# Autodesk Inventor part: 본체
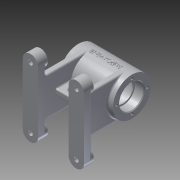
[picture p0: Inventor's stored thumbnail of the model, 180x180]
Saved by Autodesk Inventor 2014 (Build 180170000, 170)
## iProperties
Created: 2015-11
Part Number: 본체
Material: 알루미늄 6061
Document SubType Name: Modeling
Designer: Owner
Density: 2.71 g/cm^3
Appearance: 알루미늄 - 평지
Mass: 358.863 g
Surface Area: 459.993 cm^2
Volume: 132.422 cm^3
Author: Owner
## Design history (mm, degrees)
sketch "스케치1"
  geometry: L1 (-40, 50)-(-20, 50); L2 (-20, 50)-(-20, -50); L3 (-20, -50)-(-40, -50); L4 (-40, -50)-(-40, 50); L5 (40, 50)-(20, 50); L6 (20, 50)-(20, -50); L7 (20, -50)-(40, -50); L8 (40, -50)-(40, 50); 3 further points
  constraints: 16 end point, 2 parallel, 1 horizontal, 1 horizontal alignment, 1 midpoint, 1 perpendicular
  dimensions: "d0" = 100 distance of L1.end L2.end; "d1" = 20 distance of L1.start L1.end
extrude "돌출1" new body sketch "스케치1" distance "d3" = 10; taper "d4" = 0 deg
sketch "스케치2"
  geometry: L1 (68, 39.159)-(68, -46.601); L2 (0, -50)-(0, 50) reference; L3 (0, 0)-(77.376, 0); C1 r 25 at (68, 0)
  constraints: 4 end point, 2 point on line, 1 centre point, 1 perpendicular, 1 vertical
  dimensions: "d5" = 68 distance between parallel lines of L2 L1; "d6" = 50 diameter of C1
extrude "돌출2" join sketch "스케치2" stored distance "d7" = 70; taper "d8" = 0 deg
sketch "스케치3"
  geometry: C1 r 25 at (0, 0) reference; C2 r 16 at (0, 0); 1 further point
  constraints: 1 centre point, 1 coincident
  dimensions: "d9" = 32 diameter of C2
extrude "돌출3" cut sketch "스케치3" distance "d10" = 12; taper "d11" = 0 deg
sketch "스케치4"
  geometry: C1 r 16 at (0, 0) reference; 1 further point
sketch "스케치5"
  geometry: C1 r 25 at (0, 0) reference; C2 r 16 at (0, 0); 1 further point
  constraints: 1 centre point, 1 coincident
  dimensions: "d12" = 32 diameter of C2
extrude "돌출4" cut sketch "스케치5" distance "d13" = 12; taper "d14" = 0 deg
sketch "스케치6"
  geometry: C1 r 25 at (68, 0) reference; C2 r 21 at (68, 0); 1 further point
  constraints: 1 centre point, 1 coincident
  dimensions: "d15" = 42 diameter of C2
extrude "돌출5" cut sketch "스케치6" stored distance "d16" = 42; taper "d17" = 0 deg
sketch "스케치7"
  geometry: C1 r 16 at (0, 0) reference; C2 r 14 at (0, 0); 1 further point
  constraints: 1 centre point, 1 coincident
  dimensions: "d18" = 28 diameter of C2
extrude "돌출6" cut sketch "스케치7" distance "d19" = 100; taper "d20" = 0 deg
sketch "스케치9"
  geometry: L1 (-40, -50)-(-20, -50) reference; L2 (-20, -50)-(-20, 50) reference; L3 (-20, 50)-(-40, 50) reference; L4 (-40, 50)-(-40, -50) reference; 1 further point
sketch "스케치10"
  geometry: L1 (-20, -50)-(-20, 50) reference; L2 (-28, 25)-(-20, 25); L3 (-20, 25)-(-20, -25); L4 (-20, -25)-(-28, -25); L5 (-28, -25)-(-28, 25); L6 (0, 1.334)-(0, 18.077); L7 (28, 25)-(20, 25); L8 (20, 25)-(20, -25); L9 (20, -25)-(28, -25); L10 (28, -25)-(28, 25); 3 further points
  constraints: 18 end point, 5 symmetric about line, 3 parallel, 1 horizontal, 1 horizontal alignment, 1 midpoint, 1 perpendicular, 1 point on line
  dimensions: "d23" = 50 distance of L4.end L2.start; "d24" = 8 distance of L2.start L2.end
extrude "돌출7" join sketch "스케치10" stored distance "d25" = 10; taper "d26" = 0 deg
node "작업 평면2"
  node "작업 평면1"
sketch "스케치11"
  geometry: L1 (-22.5, 4)-(22.5, 4); L2 (22.5, 4)-(22.5, -4); L3 (22.5, -4)-(-22.5, -4); L4 (-22.5, -4)-(-22.5, 4); 3 further points
  constraints: 8 end point, 2 midpoint, 2 parallel, 1 horizontal, 1 horizontal alignment, 1 perpendicular, 1 vertical alignment
  dimensions: "d28" = 8 distance of L1.end L2.end; "d29" = 45 distance of L1.start L1.end
extrude "돌출8" join sketch "스케치11" stored distance "d30" = 10; taper "d31" = 0 deg
sketch "스케치12"
  geometry: L1 (40, -23)-(60, -23) reference; L2 (20, -13)-(20, -6.454); L3 (28, 6.5)-(12, 6.5); L4 (28, 13.5)-(12, 13.5); A1 r 3.5 centre (28, 10) between (28, 6.5) and (28, 13.5); A2 r 3.5 centre (12, 10) between (12, 13.5) and (12, 6.5); 1 further point
  constraints: 6 end point, 4 point on circle, 2 centre point, 2 tangent, 1 symmetric about line, 1 other
  dimensions: "d34" = 7 diameter of A1
extrude "돌출9" cut sketch "스케치12" distance "d35" = 50; taper "d36" = 0 deg
node "작업 평면4"
  node "작업 평면3"
sketch "스케치13"
  geometry: C1 r 5 at (0, 0); 1 further point
  constraints: 1 centre point, 1 coincident
  dimensions: "d38" = 10 diameter of C1
extrude "돌출10" join sketch "스케치13" stored distance "d39" = 50; taper "d40" = 0 deg
sketch "스케치14"
  geometry: L1 (68, 0)-(43.751, -14); L2 (68, 0)-(96, 0); C1 r 25 at (68, 0) reference; 1 further point
  constraints: 4 end point, 1 equal length, 1 horizontal
  dimensions: "d41" = 28 distance of L1.start L1.end; "d42" = 150 deg angle of L1 L2
node "작업 평면5"
sketch "스케치15"
  geometry: C1 r 6 at (0, 0); 1 further point
  constraints: 1 centre point
  dimensions: "d43" = 12 diameter of C1
extrude "돌출11" join sketch "스케치15" stored distance "d44" = 50; taper "d45" = 0 deg
sketch "스케치16"
  geometry: L1 (-20, 50)-(-40, 50) reference; L2 (-40, -50)-(-20, -50) reference; L3 (40, 50)-(20, 50) reference; L4 (20, -50)-(40, -50) reference; C1 r 10 at (-30, -40); C2 r 10 at (-30, 40); C3 r 10 at (30, 40); C4 r 10 at (30, -40); 5 further points
  constraints: 4 centre point, 4 midpoint, 4 vertical alignment
  dimensions: "d46" = 20 diameter of C1; "d47" = 10 distance of C1.centre point (-30, -50); "d48" = 20 diameter of C2; "d49" = 10 distance from line of L1 C2.centre; "d50" = 20 diameter of C3; "d51" = 10 distance from line of L3 C3.centre; "d52" = 20 diameter of C4; "d53" = 10 distance from line of L4 C4.centre
extrude "돌출12" join sketch "스케치16" distance "d54" = 3; taper "d55" = 0 deg
sketch "스케치17"
  geometry: C1 r 5 at (0, 0) reference; 1 further point
  constraints: 1 coincident
hole "구멍1" sketch "스케치17" at (0, 0) diameter "d56" = 5.188; stored, may be unused: countersink angle "d60" = 90 deg, drill point angle "d62" = 118 deg; dims "d57" = 20, "d58" = 4, "d59" = 2, "d61" = 20
sketch "스케치18"
  geometry: C1 r 6 at (0, 0) reference; 2 further points
  constraints: 1 coincident
hole "구멍2" sketch "스케치18" at (0, 0) diameter "d63" = 5.188; stored, may be unused: countersink angle "d67" = 90 deg, drill point angle "d69" = 118 deg; dims "d64" = 20, "d65" = 4, "d66" = 2, "d68" = 20
sketch "스케치19"
  geometry: L1 (-30, 40)-(-16.576, 40); L2 (-30, 43.111)-(-30, 78.702); C1 r 10 at (0, 0) reference; C2 r 6 at (0, 0); C3 r 6 at (0, 80); C4 r 6 at (-60, 80); C5 r 6 at (-60, 0)
  constraints: 4 centre point, 4 end point, 3 symmetric about line, 1 coincident, 1 horizontal, 1 perpendicular, 3 other
  dimensions: "d70" = 12 diameter of C2
extrude "돌출13" cut sketch "스케치19" distance "d71" = 4; taper "d72" = 0 deg
sketch "스케치20"
  geometry: L1 (-30, 40)-(-22.961, 40); L2 (-30, 42.79)-(-30, 79.412); C1 r 6 at (0, 0) reference; C2 r 3 at (0, 0); C3 r 3 at (0, 80); C4 r 3 at (-60, 80); C5 r 3 at (-60, 0)
  constraints: 4 centre point, 4 end point, 3 symmetric about line, 1 coincident, 1 horizontal, 1 perpendicular, 3 other
  dimensions: "d73" = 6 diameter of C2
extrude "돌출14" cut sketch "스케치20" distance "d74" = 20; taper "d75" = 0 deg
node "작업 평면6"
sketch "스케치21"
  geometry: L1 (-20.606, 3.48)-(20.606, 3.48); L2 (20.606, 3.48)-(20.606, -3.48); L3 (20.606, -3.48)-(-20.606, -3.48); L4 (-20.606, -3.48)-(-20.606, 3.48); L5 (-20.606, 0)-(20.606, 0); L6 (-35, 25)-(35, 25) reference; L7 (0, 3.48)-(0, -3.48); L8 (-35, 25)-(-35, -25) reference; 1 further point
  constraints: 4 end point, 4 midpoint, 2 other
  dimensions: "d76" = 25 distance between parallel lines of L6 L5; "d77" = 35 distance between parallel lines of L8 L7
feature "엠보싱1" sketch "스케치21" dims "d78" = 0.5, "d79" = 0
chamfer "모따기1" distance "d81" = 1; stored, may be unused: second distance "d82" = 2, angle "d83" = 45 deg
sketch "스케치22"
  geometry: C1 r 17 at (0, 0) reference; A1 r 20 centre (0, 0) between (0, 20) and (20, 0); 3 further points
  constraints: 4 point on circle, 1 centre point, 1 coincident
  dimensions: "d84" = 40 diameter of A1
hole "구멍3" sketch "스케치22" at (0, 20), (20, 0), (0, -20), (-20, 0) diameter "d85" = 3.242; stored, may be unused: countersink angle "d89" = 90 deg, drill point angle "d91" = 118 deg; dims "d86" = 8, "d87" = 4, "d88" = 2, "d90" = 10
sketch "스케치23"
  geometry: C1 r 17 at (0, 0) reference; A1 r 20 centre (0, 0) between (0, 20) and (20, 0); 3 further points
  constraints: 4 point on circle, 1 centre point, 1 coincident
  dimensions: "d92" = 40 diameter of A1
hole "구멍4" sketch "스케치23" at (0, 20), (20, 0), (0, -20), (-20, 0) diameter "d93" = 3.242; stored, may be unused: countersink angle "d97" = 90 deg, drill point angle "d99" = 118 deg; dims "d94" = 8, "d95" = 4, "d96" = 2, "d98" = 10
fillet "모깎기2" dims "d100" = 10, "d101" = 3, "d102" = 0.3
fillet "모깎기3" dims "d103" = 2
fillet "모깎기4" dims "d104" = 0.3
node "솔리드1"
other parameters: "d37" = 3
